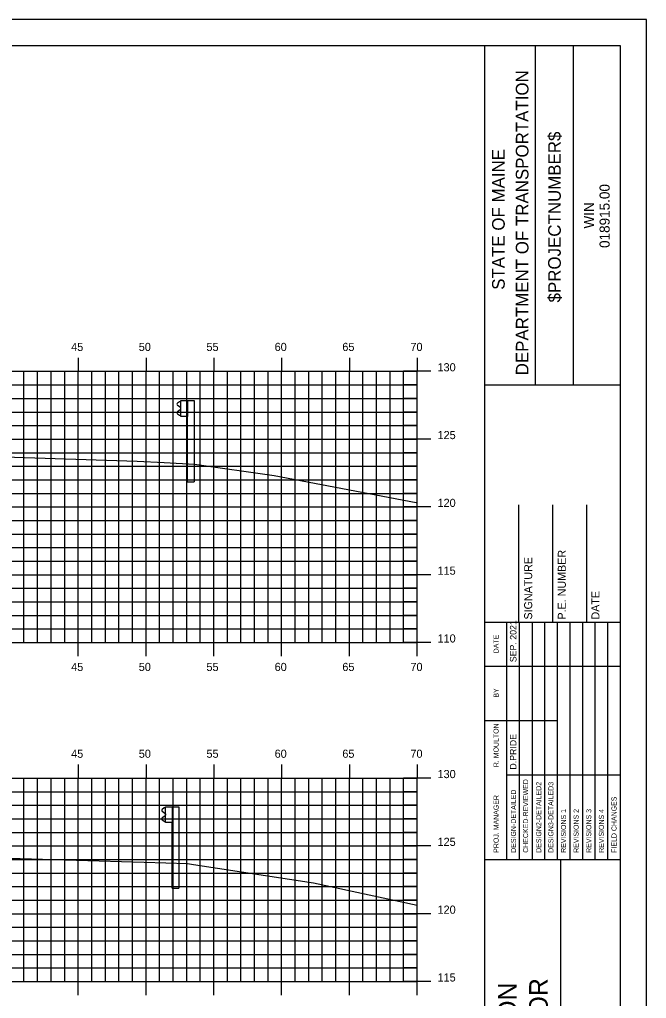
# Model space of a CAD drawing. Extents: x 852182 to 852354, y 365624 to 365734.
# Drawn here: x 852305.7 to 852351.9, y 365661.8 to 365734 of the extents above; entities that cross this region are included whole.
import ezdxf

# ---------------------------------------------------------------- set-up
doc = ezdxf.new("R2010")
doc.units = 0
for name, color, linetype in [('BORDER', 7, 'Continuous'), ('H_V ANNOTATION', 7, 'Continuous'), ('M_Guardrail', 7, 'Continuous'), ('MAJOR', 7, 'Continuous'), ('MINOR', 7, 'Continuous'), ('PLOT BOUNDARY', 7, 'Continuous'), ('S_Roadway_Centerline', 7, 'Continuous')]:
    doc.layers.add(name, color=color, linetype=linetype)

msp = doc.modelspace()

# ---------------------------------------------------------------- linework, layer by layer
at = {"layer": 'BORDER'}
for p, q in [((852340.035, 365627.027), (852340.035, 365732.027)), ((852343.764, 365707.024), (852343.764, 365732.024)), ((852346.559, 365707.024), (852346.559, 365732.024)), ((852340.036, 365707.021), (852350.035, 365707.021)), ((852342.535, 365689.53), (852342.535, 365698.177)), ((852345.035, 365689.53), (852345.035, 365698.177)), ((852347.535, 365689.53), (852347.535, 365698.177)), ((852340.035, 365689.53), (852350.035, 365689.53)), ((852340.035, 365672.03), (852350.035, 365672.03)), ((852345.627, 365637.03), (852345.627, 365672.03))]:
    msp.add_line(p, q, dxfattribs=at)
msp.add_lwpolyline([(852190.035, 365627.027), (852350.035, 365627.027), (852350.035, 365732.027), (852190.035, 365732.027)], close=True, dxfattribs=at)
for points in [[(852341.65, 365686.28), (852341.65, 365689.53)], [(852342.583, 365672.033), (852342.583, 365689.53)], [(852343.515, 365689.53), (852343.515, 365672.033)], [(852344.446, 365672.033), (852344.446, 365689.53)], [(852345.378, 365672.033), (852345.378, 365689.53)], [(852346.31, 365672.033), (852346.31, 365689.53)], [(852347.241, 365672.033), (852347.241, 365689.53)], [(852348.173, 365672.033), (852348.173, 365689.53)], [(852349.105, 365672.033), (852349.105, 365689.53)], [(852341.651, 365672.033), (852341.651, 365688.824)], [(852340.035, 365686.28), (852350.035, 365686.28)], [(852340.035, 365682.28), (852341.651, 365682.28)], [(852341.65, 365682.28), (852345.377, 365682.28)], [(852341.65, 365678.28), (852350.035, 365678.28)]]:
    msp.add_lwpolyline(points, dxfattribs=at)
at = {"layer": 'M_Guardrail'}
for p, q in [((852317.495, 365705.778), (852317.351, 365705.678)), ((852317.593, 365705.799), (852317.511, 365705.785)), ((852317.593, 365705.872), (852318.083, 365705.872)), ((852317.593, 365704.705), (852317.593, 365705.872)), ((852318.083, 365705.872), (852318.575, 365705.872)), ((852318.083, 365705.872), (852318.083, 365704.705)), ((852318.575, 365705.872), (852318.575, 365699.872)), ((852317.351, 365705.535), (852317.546, 365705.399)), ((852317.546, 365705.179), (852317.351, 365705.043)), ((852317.58, 365705.334), (852317.58, 365705.243)), ((852317.351, 365704.9), (852317.495, 365704.8)), ((852317.511, 365704.793), (852317.593, 365704.778)), ((852318.083, 365704.705), (852317.593, 365704.705)), ((852318.083, 365699.872), (852318.083, 365704.705)), ((852318.083, 365699.872), (852318.575, 365699.872)), ((852316.381, 365675.825), (852316.238, 365675.725)), ((852316.238, 365675.582), (852316.433, 365675.446)), ((852316.48, 365675.846), (852316.398, 365675.832)), ((852316.467, 365675.381), (852316.467, 365675.29)), ((852316.48, 365675.919), (852316.97, 365675.919)), ((852316.48, 365674.753), (852316.48, 365675.919)), ((852316.97, 365675.919), (852317.461, 365675.919)), ((852316.97, 365675.919), (852316.97, 365674.753)), ((852317.461, 365675.919), (852317.461, 365669.919)), ((852316.433, 365675.226), (852316.238, 365675.09)), ((852316.238, 365674.947), (852316.381, 365674.847)), ((852316.398, 365674.84), (852316.48, 365674.825)), ((852316.97, 365674.753), (852316.48, 365674.753)), ((852316.97, 365669.919), (852316.97, 365674.753)), ((852316.97, 365669.919), (852317.461, 365669.919))]:
    msp.add_line(p, q, dxfattribs=at)
for centre, major_axis, start_param, end_param in [((852317.401, 365705.606), (-0.0877, 0), 5.323254, 7.243116), ((852317.518, 365705.744), (-0.0417, 0), 4.886922, 5.323254), ((852317.401, 365704.971), (-0.0877, 0), 5.323254, 7.243116), ((852317.501, 365705.334), (0.0789, 0), 0, 0.959931), ((852317.501, 365705.243), (0.0789, 0), 5.323254, 6.283185), ((852317.518, 365704.834), (-0.0417, 0), 0.959931, 1.396263), ((852316.288, 365675.654), (-0.0877, 0), 5.323254, 7.243116), ((852316.405, 365675.791), (-0.0417, 0), 4.886922, 5.323254), ((852316.388, 365675.381), (0.0789, 0), 0, 0.959931), ((852316.288, 365675.018), (-0.0877, 0), 5.323254, 7.243116), ((852316.405, 365674.881), (-0.0417, 0), 0.959931, 1.396263), ((852316.388, 365675.29), (0.0789, 0), 5.323254, 6.283185)]:
    msp.add_ellipse(centre, major_axis=major_axis, ratio=0.995501, start_param=start_param, end_param=end_param, dxfattribs=at)
at = {"layer": 'MAJOR'}
for p, q in [((852310.035, 365709.029), (852310.035, 365708.027)), ((852315.035, 365709.029), (852315.035, 365708.027)), ((852320.035, 365709.029), (852320.035, 365708.027)), ((852325.035, 365709.029), (852325.035, 365708.027)), ((852330.035, 365709.029), (852330.035, 365708.027)), ((852335.035, 365709.029), (852335.035, 365708.027)), ((852195.035, 365708.027), (852335.035, 365708.027)), ((852195.035, 365708.027), (852335.035, 365708.027)), ((852310.035, 365688.027), (852310.035, 365708.027)), ((852315.035, 365688.027), (852315.035, 365708.027)), ((852320.035, 365688.027), (852320.035, 365708.027)), ((852325.035, 365688.027), (852325.035, 365708.027)), ((852330.035, 365688.027), (852330.035, 365708.027)), ((852336.037, 365708.027), (852334.033, 365708.027)), ((852335.035, 365688.027), (852335.035, 365708.027)), ((852335.035, 365688.027), (852335.035, 365708.027)), ((852195.035, 365703.027), (852335.035, 365703.027)), ((852336.037, 365703.027), (852334.033, 365703.027)), ((852195.035, 365698.027), (852335.035, 365698.027)), ((852336.037, 365698.027), (852334.033, 365698.027)), ((852195.035, 365693.027), (852335.035, 365693.027)), ((852336.037, 365693.027), (852334.033, 365693.027)), ((852195.035, 365688.027), (852335.035, 365688.027)), ((852195.035, 365688.027), (852335.035, 365688.027)), ((852310.035, 365687.025), (852310.035, 365688.027)), ((852315.035, 365687.025), (852315.035, 365688.027)), ((852320.035, 365687.025), (852320.035, 365688.027)), ((852325.035, 365687.025), (852325.035, 365688.027)), ((852330.035, 365687.025), (852330.035, 365688.027)), ((852336.037, 365688.027), (852334.033, 365688.027)), ((852335.035, 365687.025), (852335.035, 365688.027)), ((852310.035, 365679.029), (852310.035, 365678.027)), ((852315.035, 365679.029), (852315.035, 365678.027)), ((852320.035, 365679.029), (852320.035, 365678.027)), ((852325.035, 365679.029), (852325.035, 365678.027)), ((852330.035, 365679.029), (852330.035, 365678.027)), ((852335.035, 365679.029), (852335.035, 365678.027)), ((852195.035, 365678.027), (852335.035, 365678.027)), ((852195.035, 365678.027), (852335.035, 365678.027)), ((852310.035, 365663.027), (852310.035, 365678.027)), ((852315.035, 365663.027), (852315.035, 365678.027)), ((852320.035, 365663.027), (852320.035, 365678.027)), ((852325.035, 365663.027), (852325.035, 365678.027)), ((852330.035, 365663.027), (852330.035, 365678.027)), ((852336.037, 365678.027), (852334.033, 365678.027)), ((852335.035, 365663.027), (852335.035, 365678.027)), ((852335.035, 365663.027), (852335.035, 365678.027)), ((852195.035, 365673.027), (852335.035, 365673.027)), ((852336.037, 365673.027), (852334.033, 365673.027)), ((852195.035, 365668.027), (852335.035, 365668.027)), ((852336.037, 365668.027), (852334.033, 365668.027)), ((852195.035, 365663.027), (852335.035, 365663.027)), ((852195.035, 365663.027), (852335.035, 365663.027)), ((852310.035, 365662.025), (852310.035, 365663.027)), ((852315.035, 365662.025), (852315.035, 365663.027)), ((852320.035, 365662.025), (852320.035, 365663.027)), ((852325.035, 365662.025), (852325.035, 365663.027)), ((852330.035, 365662.025), (852330.035, 365663.027)), ((852336.037, 365663.027), (852334.033, 365663.027)), ((852335.035, 365662.025), (852335.035, 365663.027))]:
    msp.add_line(p, q, dxfattribs=at)
at = {"layer": 'MINOR'}
for p, q in [((852306.035, 365688.027), (852306.035, 365708.027)), ((852307.035, 365688.027), (852307.035, 365708.027)), ((852308.035, 365688.027), (852308.035, 365708.027)), ((852309.035, 365688.027), (852309.035, 365708.027)), ((852311.035, 365688.027), (852311.035, 365708.027)), ((852312.035, 365688.027), (852312.035, 365708.027)), ((852313.035, 365688.027), (852313.035, 365708.027)), ((852314.035, 365688.027), (852314.035, 365708.027)), ((852316.035, 365688.027), (852316.035, 365708.027)), ((852317.035, 365688.027), (852317.035, 365708.027)), ((852318.035, 365688.027), (852318.035, 365708.027)), ((852319.035, 365688.027), (852319.035, 365708.027)), ((852321.035, 365688.027), (852321.035, 365708.027)), ((852322.035, 365688.027), (852322.035, 365708.027)), ((852323.035, 365688.027), (852323.035, 365708.027)), ((852324.035, 365688.027), (852324.035, 365708.027)), ((852326.035, 365688.027), (852326.035, 365708.027)), ((852327.035, 365688.027), (852327.035, 365708.027)), ((852328.035, 365688.027), (852328.035, 365708.027)), ((852329.035, 365688.027), (852329.035, 365708.027)), ((852331.035, 365688.027), (852331.035, 365708.027)), ((852332.035, 365688.027), (852332.035, 365708.027)), ((852333.035, 365688.027), (852333.035, 365708.027)), ((852334.035, 365688.027), (852334.035, 365708.027)), ((852195.035, 365707.027), (852335.035, 365707.027)), ((852335.035, 365707.027), (852334.033, 365707.027)), ((852195.035, 365706.027), (852335.035, 365706.027)), ((852335.035, 365706.027), (852334.033, 365706.027)), ((852195.035, 365705.027), (852335.035, 365705.027)), ((852335.035, 365705.027), (852334.033, 365705.027)), ((852195.035, 365704.027), (852335.035, 365704.027)), ((852335.035, 365704.027), (852334.033, 365704.027)), ((852195.035, 365702.027), (852335.035, 365702.027)), ((852335.035, 365702.027), (852334.033, 365702.027)), ((852195.035, 365701.027), (852335.035, 365701.027)), ((852335.035, 365701.027), (852334.033, 365701.027)), ((852195.035, 365700.027), (852335.035, 365700.027)), ((852335.035, 365700.027), (852334.033, 365700.027)), ((852195.035, 365699.027), (852335.035, 365699.027)), ((852335.035, 365699.027), (852334.033, 365699.027)), ((852195.035, 365697.027), (852335.035, 365697.027)), ((852335.035, 365697.027), (852334.033, 365697.027)), ((852195.035, 365696.027), (852335.035, 365696.027)), ((852335.035, 365696.027), (852334.033, 365696.027)), ((852195.035, 365695.027), (852335.035, 365695.027)), ((852335.035, 365695.027), (852334.033, 365695.027)), ((852195.035, 365694.027), (852335.035, 365694.027)), ((852335.035, 365694.027), (852334.033, 365694.027)), ((852195.035, 365692.027), (852335.035, 365692.027)), ((852335.035, 365692.027), (852334.033, 365692.027)), ((852195.035, 365691.027), (852335.035, 365691.027)), ((852335.035, 365691.027), (852334.033, 365691.027)), ((852195.035, 365690.027), (852335.035, 365690.027)), ((852335.035, 365690.027), (852334.033, 365690.027)), ((852195.035, 365689.027), (852335.035, 365689.027)), ((852335.035, 365689.027), (852334.033, 365689.027)), ((852306.035, 365663.027), (852306.035, 365678.027)), ((852307.035, 365663.027), (852307.035, 365678.027)), ((852308.035, 365663.027), (852308.035, 365678.027)), ((852309.035, 365663.027), (852309.035, 365678.027)), ((852311.035, 365663.027), (852311.035, 365678.027)), ((852312.035, 365663.027), (852312.035, 365678.027)), ((852313.035, 365663.027), (852313.035, 365678.027)), ((852314.035, 365663.027), (852314.035, 365678.027)), ((852316.035, 365663.027), (852316.035, 365678.027)), ((852317.035, 365663.027), (852317.035, 365678.027)), ((852318.035, 365663.027), (852318.035, 365678.027)), ((852319.035, 365663.027), (852319.035, 365678.027)), ((852321.035, 365663.027), (852321.035, 365678.027)), ((852322.035, 365663.027), (852322.035, 365678.027)), ((852323.035, 365663.027), (852323.035, 365678.027)), ((852324.035, 365663.027), (852324.035, 365678.027)), ((852326.035, 365663.027), (852326.035, 365678.027)), ((852327.035, 365663.027), (852327.035, 365678.027)), ((852328.035, 365663.027), (852328.035, 365678.027)), ((852329.035, 365663.027), (852329.035, 365678.027)), ((852331.035, 365663.027), (852331.035, 365678.027)), ((852332.035, 365663.027), (852332.035, 365678.027)), ((852333.035, 365663.027), (852333.035, 365678.027)), ((852334.035, 365663.027), (852334.035, 365678.027)), ((852195.035, 365677.027), (852335.035, 365677.027)), ((852335.035, 365677.027), (852334.033, 365677.027)), ((852195.035, 365676.027), (852335.035, 365676.027)), ((852335.035, 365676.027), (852334.033, 365676.027)), ((852195.035, 365675.027), (852335.035, 365675.027)), ((852335.035, 365675.027), (852334.033, 365675.027)), ((852195.035, 365674.027), (852335.035, 365674.027)), ((852335.035, 365674.027), (852334.033, 365674.027)), ((852195.035, 365672.027), (852335.035, 365672.027)), ((852335.035, 365672.027), (852334.033, 365672.027)), ((852195.035, 365671.027), (852335.035, 365671.027)), ((852335.035, 365671.027), (852334.033, 365671.027)), ((852195.035, 365670.027), (852335.035, 365670.027)), ((852335.035, 365670.027), (852334.033, 365670.027)), ((852195.035, 365669.027), (852335.035, 365669.027)), ((852335.035, 365669.027), (852334.033, 365669.027)), ((852195.035, 365667.027), (852335.035, 365667.027)), ((852335.035, 365667.027), (852334.033, 365667.027)), ((852195.035, 365666.027), (852335.035, 365666.027)), ((852335.035, 365666.027), (852334.033, 365666.027)), ((852195.035, 365665.027), (852335.035, 365665.027)), ((852335.035, 365665.027), (852334.033, 365665.027)), ((852195.035, 365664.027), (852335.035, 365664.027)), ((852335.035, 365664.027), (852334.033, 365664.027))]:
    msp.add_line(p, q, dxfattribs=at)
at = {"layer": 'PLOT BOUNDARY'}
msp.add_lwpolyline([(852181.942, 365623.968), (852351.942, 365623.968), (852351.942, 365733.968), (852181.942, 365733.968)], close=True, dxfattribs=at)
at = {"layer": 'S_Roadway_Centerline'}
for points in [[(852256.687, 365699.838), (852261.621, 365700.327), (852273.269, 365701.47), (852274.137, 365701.506), (852287.45, 365701.841), (852292.981, 365701.992), (852293.529, 365702.032), (852294.212, 365702.018), (852297.012, 365701.969), (852314.385, 365701.407), (852316.37, 365701.301), (852318.61, 365701.183), (852324.48, 365700.337), (852334.948, 365698.342), (852335.035, 365698.321)], [(852254.618, 365670.011), (852262.427, 365670.97), (852267.878, 365671.488), (852271.682, 365671.768), (852274.775, 365671.918), (852276.815, 365671.956), (852281.912, 365672.15), (852283.501, 365672.194), (852290.788, 365672.344), (852292.581, 365672.368), (852293.095, 365672.356), (852301.638, 365672.231), (852302.92, 365672.209), (852304.916, 365672.121), (852314.905, 365671.829), (852318.092, 365671.724), (852318.539, 365671.667), (852327.398, 365670.308), (852335.035, 365668.663)]]:
    msp.add_lwpolyline(points, dxfattribs=at)

# ---------------------------------------------------------------- texts
at = {"layer": 'BORDER'}
for s, height, p in [('DEPARTMENT OF TRANSPORTATION', 0.93176, (852343.242, 365707.733)), ('$PROJECTNUMBER$', 0.93176, (852345.627, 365713.106)), ('STATE OF MAINE', 0.93176, (852341.491, 365714.039)), ('018915.00', 0.7453, (852349.231, 365717.125)), ('WIN', 0.7453, (852348.072, 365718.557)), ('P.E. NUMBER', 0.59055, (852345.996, 365689.722)), ('SIGNATURE', 0.5906, (852343.516, 365689.722)), ('DATE', 0.5906, (852348.477, 365689.722)), ('SEP. 2021', 0.4845, (852342.358, 365686.575)), ('DATE', 0.3714, (852341.04, 365687.235)), ('BY', 0.3714, (852341.04, 365683.965)), ('R. MOULTON', 0.3727, (852341.039, 365678.832)), ('D.PRIDE', 0.4845, (852342.358, 365678.653)), ('CHECKED-REVIEWED', 0.37275, (852343.216, 365672.518)), ('DESIGN2-DETAILED2', 0.37275, (852344.185, 365672.518)), ('DESIGN3-DETAILED3', 0.37275, (852345.08, 365672.518)), ('DESIGN-DETAILED', 0.37275, (852342.322, 365672.518)), ('PROJ. MANAGER', 0.37275, (852341.04, 365672.518)), ('FIELD CHANGES', 0.37275, (852349.738, 365672.518)), ('REVISIONS 1', 0.37275, (852346.012, 365672.518)), ('REVISIONS 2', 0.37275, (852346.943, 365672.518)), ('REVISIONS 3', 0.37275, (852347.875, 365672.518)), ('REVISIONS 4', 0.37275, (852348.807, 365672.518)), ('I-395/ROUTE 9 CONNECTOR', 1.37787, (852344.67, 365638.192)), ('BREWER TO EDDINGTON', 1.37787, (852342.369, 365640.231))]:
    msp.add_text(s, height=height, rotation=90, dxfattribs=at).set_placement(p)
at = {"layer": 'H_V ANNOTATION'}
for s, p in [('45', (852309.513, 365709.527)), ('50', (852314.5, 365709.527)), ('55', (852319.492, 365709.527)), ('60', (852324.521, 365709.527)), ('65', (852329.513, 365709.527)), ('70', (852334.537, 365709.527)), ('130', (852336.535, 365708.027)), ('125', (852336.535, 365703.027)), ('120', (852336.535, 365698.027)), ('115', (852336.535, 365693.027)), ('110', (852336.535, 365688.027)), ('45', (852309.513, 365685.927)), ('50', (852314.5, 365685.927)), ('55', (852319.492, 365685.927)), ('60', (852324.521, 365685.927)), ('65', (852329.513, 365685.927)), ('70', (852334.537, 365685.927)), ('45', (852309.513, 365679.527)), ('50', (852314.5, 365679.527)), ('55', (852319.492, 365679.527)), ('60', (852324.521, 365679.527)), ('65', (852329.513, 365679.527)), ('70', (852334.537, 365679.527)), ('130', (852336.535, 365678.027)), ('125', (852336.535, 365673.027)), ('120', (852336.535, 365668.027)), ('115', (852336.535, 365663.027))]:
    msp.add_text(s, height=0.6, dxfattribs=at).set_placement(p)

doc.saveas('drawing.dxf')
